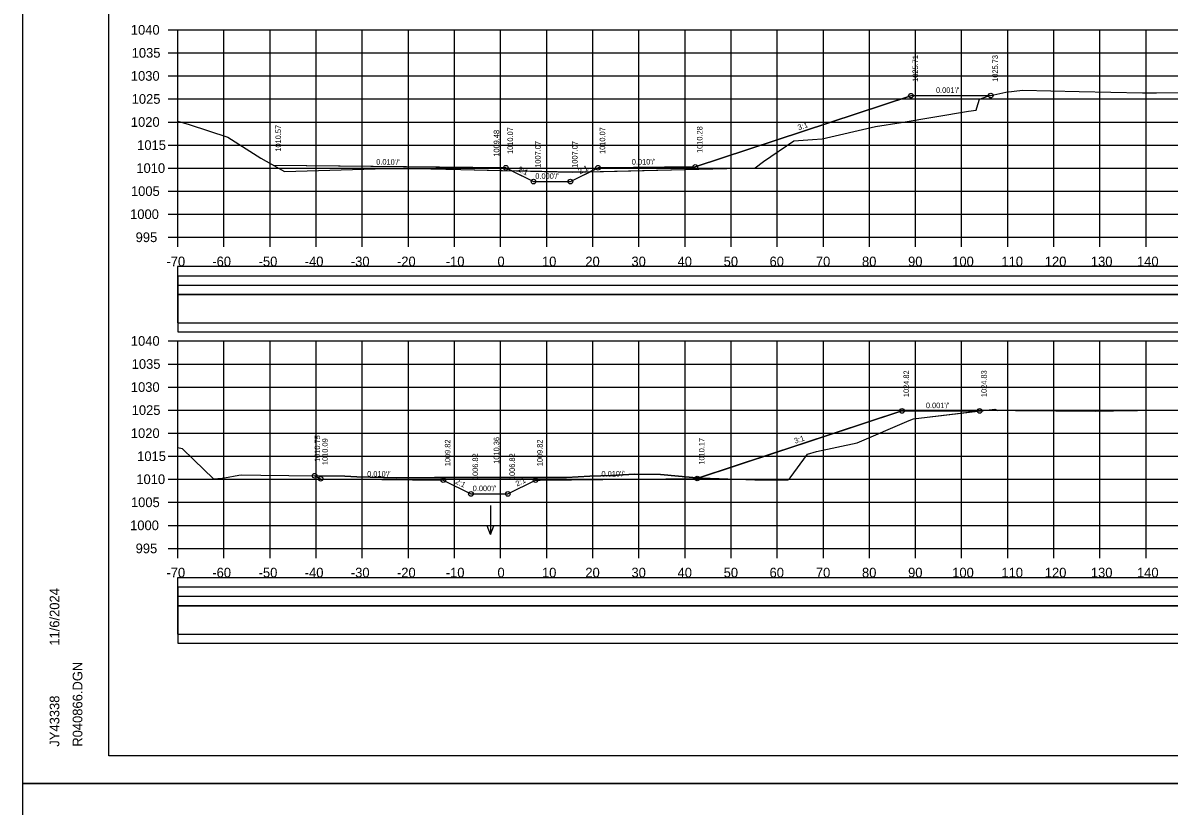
# Model space of a CAD drawing. Extents: x 1370565 to 1374448, y 301010 to 304637.
# Drawn here: x 1373947.9 to 1374196.5, y 302368.1 to 302538 of the extents above; entities that cross this region are included whole.
import ezdxf

# ---------------------------------------------------------------- set-up
doc = ezdxf.new("R2010")
doc.units = 0
for name, color, linetype in [('Default', 7, 'Continuous'), ('R_Axis', 7, 'Continuous'), ('R_Axis Annot', 7, 'Continuous'), ('R_Border', 7, 'Continuous'), ('R_Contours', 7, 'Continuous'), ('R_Drive', 7, 'Continuous'), ('R_Exist Surface', 7, 'Continuous'), ('R_Fin Surface', 7, 'Continuous'), ('R_Grid', 7, 'Continuous'), ('R_No Plot', 7, 'Continuous'), ('R_Water Annot', 7, 'Continuous'), ('R_Xsect Elev', 7, 'Continuous'), ('R_Xsect Slope', 7, 'Continuous')]:
    doc.layers.add(name, color=color, linetype=linetype)

msp = doc.modelspace()

# ---------------------------------------------------------------- linework, layer by layer
at = {"layer": 'Default'}
for points in [[(1373981.44, 302481.11), (1374421.61, 302481.11), (1374421.61, 302485.1), (1373981.44, 302485.1)], [(1373981.44, 302472.88), (1374421.61, 302472.88), (1374421.61, 302481.02), (1373981.44, 302481.02)], [(1373981.44, 302413.61), (1374421.61, 302413.61), (1374421.61, 302417.6), (1373981.44, 302417.6)], [(1373981.44, 302405.38), (1374421.61, 302405.38), (1374421.61, 302413.52), (1373981.44, 302413.52)]]:
    msp.add_lwpolyline(points, close=True, dxfattribs=at)
at = {"layer": 'R_Axis'}
for p, q in [((1373979.42, 302536.48), (1373981.52, 302536.48)), ((1373981.52, 302491.48), (1373981.52, 302536.48)), ((1373979.42, 302531.48), (1373981.52, 302531.48)), ((1373979.42, 302526.48), (1373981.52, 302526.48)), ((1373979.42, 302521.48), (1373981.52, 302521.48)), ((1373979.42, 302516.48), (1373981.52, 302516.48)), ((1373979.42, 302511.48), (1373981.52, 302511.48)), ((1373979.42, 302506.48), (1373981.52, 302506.48)), ((1373979.42, 302501.48), (1373981.52, 302501.48)), ((1373979.42, 302496.48), (1373981.52, 302496.48)), ((1373979.42, 302491.48), (1373981.52, 302491.48)), ((1373981.52, 302491.48), (1374421.52, 302491.48)), ((1373981.52, 302489.38), (1373981.52, 302491.48)), ((1373991.52, 302489.38), (1373991.52, 302491.48)), ((1374001.52, 302489.38), (1374001.52, 302491.48)), ((1374011.52, 302489.38), (1374011.52, 302491.48)), ((1374021.52, 302489.38), (1374021.52, 302491.48)), ((1374031.52, 302489.38), (1374031.52, 302491.48)), ((1374041.52, 302489.38), (1374041.52, 302491.48)), ((1374051.52, 302489.38), (1374051.52, 302491.48)), ((1374061.52, 302489.38), (1374061.52, 302491.48)), ((1374071.52, 302489.38), (1374071.52, 302491.48)), ((1374081.52, 302489.38), (1374081.52, 302491.48)), ((1374091.52, 302489.38), (1374091.52, 302491.48)), ((1374101.52, 302489.38), (1374101.52, 302491.48)), ((1374111.52, 302489.38), (1374111.52, 302491.48)), ((1374121.52, 302489.38), (1374121.52, 302491.48)), ((1374131.52, 302489.38), (1374131.52, 302491.48)), ((1374141.52, 302489.38), (1374141.52, 302491.48)), ((1374151.52, 302489.38), (1374151.52, 302491.48)), ((1374161.52, 302489.38), (1374161.52, 302491.48)), ((1374171.52, 302489.38), (1374171.52, 302491.48)), ((1374181.52, 302489.38), (1374181.52, 302491.48)), ((1374191.52, 302489.38), (1374191.52, 302491.48)), ((1373979.42, 302468.98), (1373981.52, 302468.98)), ((1373981.52, 302423.98), (1373981.52, 302468.98)), ((1373979.42, 302463.98), (1373981.52, 302463.98)), ((1373979.42, 302458.98), (1373981.52, 302458.98)), ((1373979.42, 302453.98), (1373981.52, 302453.98)), ((1373979.42, 302448.98), (1373981.52, 302448.98)), ((1373979.42, 302443.98), (1373981.52, 302443.98)), ((1373979.42, 302438.98), (1373981.52, 302438.98)), ((1373979.42, 302433.98), (1373981.52, 302433.98)), ((1373979.42, 302428.98), (1373981.52, 302428.98)), ((1373979.42, 302423.98), (1373981.52, 302423.98)), ((1373981.52, 302423.98), (1374421.52, 302423.98)), ((1373981.52, 302421.88), (1373981.52, 302423.98)), ((1373991.52, 302421.88), (1373991.52, 302423.98)), ((1374001.52, 302421.88), (1374001.52, 302423.98)), ((1374011.52, 302421.88), (1374011.52, 302423.98)), ((1374021.52, 302421.88), (1374021.52, 302423.98)), ((1374031.52, 302421.88), (1374031.52, 302423.98)), ((1374041.52, 302421.88), (1374041.52, 302423.98)), ((1374051.52, 302421.88), (1374051.52, 302423.98)), ((1374061.52, 302421.88), (1374061.52, 302423.98)), ((1374071.52, 302421.88), (1374071.52, 302423.98)), ((1374081.52, 302421.88), (1374081.52, 302423.98)), ((1374091.52, 302421.88), (1374091.52, 302423.98)), ((1374101.52, 302421.88), (1374101.52, 302423.98)), ((1374111.52, 302421.88), (1374111.52, 302423.98)), ((1374121.52, 302421.88), (1374121.52, 302423.98)), ((1374131.52, 302421.88), (1374131.52, 302423.98)), ((1374141.52, 302421.88), (1374141.52, 302423.98)), ((1374151.52, 302421.88), (1374151.52, 302423.98)), ((1374161.52, 302421.88), (1374161.52, 302423.98)), ((1374171.52, 302421.88), (1374171.52, 302423.98)), ((1374181.52, 302421.88), (1374181.52, 302423.98)), ((1374191.52, 302421.88), (1374191.52, 302423.98))]:
    msp.add_line(p, q, dxfattribs=at)
at = {"layer": 'R_Border'}
for p, q in [((1373966.52, 302378.98), (1373966.52, 302687.17)), ((1373966.52, 302378.98), (1373966.52, 302378.98)), ((1374440.79, 302378.98), (1373966.52, 302378.98))]:
    msp.add_line(p, q, dxfattribs=at)
at = {"layer": 'R_Contours'}
for p, q in [((1374051.52, 302506.56), (1374002.34, 302507.05)), ((1374051.52, 302505.96), (1374051.52, 302506.56)), ((1374052.66, 302506.55), (1374051.52, 302506.56)), ((1374051.52, 302506.56), (1374051.52, 302505.96)), ((1374051.52, 302505.96), (1374053.95, 302505.9)), ((1374053.95, 302505.9), (1374052.66, 302506.55)), ((1374053.95, 302505.9), (1374058.66, 302503.55)), ((1374070.9, 302505.67), (1374094.55, 302506.26)), ((1374094.52, 302439.26), (1374094.04, 302439.28)), ((1374094.52, 302439.26), (1374095.01, 302439.25))]:
    msp.add_line(p, q, dxfattribs=at)
for points in [[(1374157.83, 302522.21), (1374140.51, 302522.19), (1374093.75, 302506.76), (1374073.66, 302506.56), (1374072.66, 302506.55), (1374070.9, 302505.67)], [(1374094.55, 302506.26), (1374106.76, 302506.54), (1374108.54, 302507.88), (1374115.11, 302512.39), (1374119.2, 302512.69), (1374121.23, 302512.83), (1374132.86, 302515.53), (1374138.39, 302516.38), (1374153.01, 302518.8), (1374154.7, 302519.04), (1374154.84, 302519.57), (1374155.09, 302520.5), (1374155.38, 302521.44), (1374157.18, 302522.06), (1374157.83, 302522.21)], [(1374002.34, 302507.05), (1374004.67, 302505.73), (1374024.32, 302506.29), (1374027.89, 302506.39), (1374028.94, 302506.42), (1374036.39, 302506.33), (1374042.91, 302506.17), (1374051.52, 302505.96)], [(1374070.9, 302505.67), (1374067.07, 302505.58), (1374053.95, 302505.9)], [(1374058.66, 302503.55), (1374066.66, 302503.55), (1374070.9, 302505.67)], [(1374155.41, 302453.81), (1374138.56, 302453.8), (1374094.52, 302439.26)], [(1374095.01, 302439.25), (1374106.67, 302438.86), (1374112.23, 302438.83), (1374113.87, 302438.82), (1374114.3, 302439.25), (1374118.11, 302444.43), (1374120.07, 302444.99), (1374128.88, 302446.87), (1374140.14, 302451.73), (1374141.06, 302452.12), (1374142.25, 302452.25), (1374155.41, 302453.81)], [(1374094.04, 302439.28), (1374093.9, 302439.29), (1374093.21, 302439.36), (1374086.2, 302440.04), (1374080.55, 302440.11), (1374075.64, 302439.8), (1374070.87, 302439.62), (1374065.84, 302439.37), (1374065.44, 302439.34), (1374054.86, 302439.34), (1374051.52, 302439.34), (1374037.17, 302439.33), (1374029.02, 302439.31), (1374020.34, 302439.53), (1374017.73, 302439.64), (1374011.17, 302439.73)], [(1374011.17, 302439.73), (1374012.49, 302439.06), (1374039.08, 302438.8), (1374045.08, 302435.8), (1374053.08, 302435.8), (1374059.08, 302438.8), (1374060.08, 302438.81), (1374094.18, 302439.15), (1374094.52, 302439.26)]]:
    msp.add_lwpolyline(points, dxfattribs=at)
at = {"layer": 'R_Drive'}
for points in [[(1373981.52, 302479.07), (1374421.73, 302479.07), (1374421.73, 302483.07), (1373981.52, 302483.07)], [(1373981.52, 302470.93), (1374421.73, 302470.93), (1374421.73, 302479.07), (1373981.52, 302479.07)], [(1373981.52, 302411.55), (1374421.73, 302411.55), (1374421.73, 302415.54), (1373981.52, 302415.54)], [(1373981.52, 302403.4), (1374421.66, 302403.4), (1374421.66, 302411.55), (1373981.52, 302411.55)]]:
    msp.add_lwpolyline(points, close=True, dxfattribs=at)
at = {"layer": 'R_Exist Surface'}
for points in [[(1373981.52, 302516.69), (1373983.97, 302515.94), (1373992.38, 302513.17), (1373999.5, 302508.66), (1374004.67, 302505.73), (1374024.32, 302506.29), (1374027.89, 302506.39), (1374028.94, 302506.42), (1374036.39, 302506.33), (1374042.91, 302506.17), (1374067.07, 302505.58), (1374094.55, 302506.26), (1374106.76, 302506.54), (1374108.54, 302507.88), (1374115.11, 302512.39), (1374119.2, 302512.69), (1374121.23, 302512.83), (1374132.86, 302515.53), (1374138.39, 302516.38), (1374153.01, 302518.8), (1374154.7, 302519.04), (1374154.84, 302519.57), (1374155.09, 302520.5), (1374155.38, 302521.44), (1374157.18, 302522.06), (1374161.07, 302522.95), (1374164.74, 302523.39), (1374176.99, 302523.11), (1374190.74, 302522.8), (1374193.8, 302522.8), (1374216.53, 302523.07)], [(1373981.52, 302445.9), (1373982.47, 302445.63), (1373984.96, 302443.18), (1373989.24, 302439.05), (1373991.1, 302439.22), (1373991.67, 302439.26), (1373994.72, 302439.83), (1373995.38, 302439.94), (1373999.49, 302439.87), (1374017.73, 302439.64), (1374020.34, 302439.53), (1374029.02, 302439.31), (1374037.17, 302439.33), (1374054.86, 302439.34), (1374065.44, 302439.34), (1374065.84, 302439.37), (1374070.87, 302439.62), (1374075.64, 302439.8), (1374080.55, 302440.11), (1374086.2, 302440.04), (1374093.21, 302439.36), (1374093.9, 302439.29), (1374094.04, 302439.28), (1374095.01, 302439.25), (1374106.67, 302438.86), (1374112.23, 302438.83), (1374113.87, 302438.82), (1374114.3, 302439.25), (1374118.11, 302444.43), (1374120.07, 302444.99), (1374128.88, 302446.87), (1374140.14, 302451.73), (1374141.06, 302452.12), (1374142.25, 302452.25), (1374158.71, 302454.2), (1374159.21, 302454), (1374159.32, 302453.86), (1374160.71, 302453.93), (1374163.18, 302453.87), (1374180.6, 302453.73), (1374184.48, 302453.83), (1374194.86, 302453.99), (1374210.81, 302454.28)]]:
    msp.add_lwpolyline(points, dxfattribs=at)
at = {"layer": 'R_Fin Surface'}
msp.add_line((1374052.66, 302506.55), (1374002.34, 302507.05), dxfattribs=at)
for points in [[(1374052.66, 302506.55), (1374058.66, 302503.55), (1374066.66, 302503.55), (1374072.66, 302506.55), (1374073.66, 302506.56), (1374093.75, 302506.76), (1374140.51, 302522.19), (1374157.83, 302522.21)], [(1374011.17, 302439.73), (1374012.49, 302439.06), (1374039.08, 302438.8), (1374045.08, 302435.8), (1374053.08, 302435.8), (1374059.08, 302438.8), (1374060.08, 302438.81), (1374094.18, 302439.15), (1374138.56, 302453.8), (1374155.41, 302453.81)]]:
    msp.add_lwpolyline(points, dxfattribs=at)
at = {"layer": 'R_Grid'}
for p, q in [((1373981.52, 302536.48), (1374421.52, 302536.48)), ((1373981.52, 302491.48), (1373981.52, 302536.48)), ((1373991.52, 302491.48), (1373991.52, 302536.48)), ((1374001.52, 302491.48), (1374001.52, 302536.48)), ((1374011.52, 302491.48), (1374011.52, 302536.48)), ((1374021.52, 302491.48), (1374021.52, 302536.48)), ((1374031.52, 302491.48), (1374031.52, 302536.48)), ((1374041.52, 302491.48), (1374041.52, 302536.48)), ((1374051.52, 302491.48), (1374051.52, 302536.48)), ((1374061.52, 302491.48), (1374061.52, 302536.48)), ((1374071.52, 302491.48), (1374071.52, 302536.48)), ((1374081.52, 302491.48), (1374081.52, 302536.48)), ((1374091.52, 302491.48), (1374091.52, 302536.48)), ((1374101.52, 302491.48), (1374101.52, 302536.48)), ((1374111.52, 302491.48), (1374111.52, 302536.48)), ((1374121.52, 302491.48), (1374121.52, 302536.48)), ((1374131.52, 302491.48), (1374131.52, 302536.48)), ((1374141.52, 302491.48), (1374141.52, 302536.48)), ((1374151.52, 302491.48), (1374151.52, 302536.48)), ((1374161.52, 302491.48), (1374161.52, 302536.48)), ((1374171.52, 302491.48), (1374171.52, 302536.48)), ((1374181.52, 302491.48), (1374181.52, 302536.48)), ((1374191.52, 302491.48), (1374191.52, 302536.48)), ((1373981.52, 302531.48), (1374421.52, 302531.48)), ((1373981.52, 302526.48), (1374421.52, 302526.48)), ((1373981.52, 302521.48), (1374421.52, 302521.48)), ((1373981.52, 302516.48), (1374421.52, 302516.48)), ((1373981.52, 302511.48), (1374421.52, 302511.48)), ((1373981.52, 302506.48), (1374421.52, 302506.48)), ((1373981.52, 302501.48), (1374421.52, 302501.48)), ((1373981.52, 302496.48), (1374421.52, 302496.48)), ((1373981.52, 302491.48), (1374421.52, 302491.48)), ((1373981.52, 302468.98), (1374421.52, 302468.98)), ((1373981.52, 302423.98), (1373981.52, 302468.98)), ((1373991.52, 302423.98), (1373991.52, 302468.98)), ((1374001.52, 302423.98), (1374001.52, 302468.98)), ((1374011.52, 302423.98), (1374011.52, 302468.98)), ((1374021.52, 302423.98), (1374021.52, 302468.98)), ((1374031.52, 302423.98), (1374031.52, 302468.98)), ((1374041.52, 302423.98), (1374041.52, 302468.98)), ((1374051.52, 302423.98), (1374051.52, 302468.98)), ((1374061.52, 302423.98), (1374061.52, 302468.98)), ((1374071.52, 302423.98), (1374071.52, 302468.98)), ((1374081.52, 302423.98), (1374081.52, 302468.98)), ((1374091.52, 302423.98), (1374091.52, 302468.98)), ((1374101.52, 302423.98), (1374101.52, 302468.98)), ((1374111.52, 302423.98), (1374111.52, 302468.98)), ((1374121.52, 302423.98), (1374121.52, 302468.98)), ((1374131.52, 302423.98), (1374131.52, 302468.98)), ((1374141.52, 302423.98), (1374141.52, 302468.98)), ((1374151.52, 302423.98), (1374151.52, 302468.98)), ((1374161.52, 302423.98), (1374161.52, 302468.98)), ((1374171.52, 302423.98), (1374171.52, 302468.98)), ((1374181.52, 302423.98), (1374181.52, 302468.98)), ((1374191.52, 302423.98), (1374191.52, 302468.98)), ((1373981.52, 302463.98), (1374421.52, 302463.98)), ((1373981.52, 302458.98), (1374421.52, 302458.98)), ((1373981.52, 302453.98), (1374421.52, 302453.98)), ((1373981.52, 302448.98), (1374421.52, 302448.98)), ((1373981.52, 302443.98), (1374421.52, 302443.98)), ((1373981.52, 302438.98), (1374421.52, 302438.98)), ((1373981.52, 302433.98), (1374421.52, 302433.98)), ((1373981.52, 302428.98), (1374421.52, 302428.98)), ((1373981.52, 302423.98), (1374421.52, 302423.98))]:
    msp.add_line(p, q, dxfattribs=at)
at = {"layer": 'R_No Plot'}
for p, q in [((1373947.92, 302373.01), (1374447.92, 302373.01)), ((1373947.92, 302373), (1374447.92, 302373))]:
    msp.add_line(p, q, dxfattribs=at)
for points in [[(1373947.91, 302693.01), (1374447.92, 302693.01), (1374447.92, 302373), (1373947.91, 302373)], [(1374317.4, 302687.17), (1374346.83, 302687.17), (1374346.83, 302672.35), (1374371, 302672.35), (1374405.8, 302672.35), (1374405.98, 302630.11), (1374440.79, 302630.11), (1374440.79, 302378.98), (1373966.52, 302378.98), (1373966.52, 302687.17)], [(1373947.91, 302373), (1374447.92, 302373), (1374447.92, 302053), (1373947.91, 302053)]]:
    msp.add_lwpolyline(points, close=True, dxfattribs=at)
for centre in [(1374157.83, 302522.21), (1374140.51, 302522.19), (1374052.66, 302506.55), (1374072.66, 302506.55), (1374093.75, 302506.76), (1374058.66, 302503.55), (1374066.66, 302503.55), (1374138.56, 302453.8), (1374155.41, 302453.81), (1374011.17, 302439.73), (1374012.49, 302439.06), (1374039.08, 302438.8), (1374059.08, 302438.8), (1374094.18, 302439.15), (1374045.08, 302435.8), (1374053.08, 302435.8)]:
    msp.add_circle(centre, 0.5, dxfattribs=at)
at = {"layer": 'R_Water Annot'}
for p, q in [((1374049.33, 302433.26), (1374049.33, 302426.97)), ((1374049.33, 302426.97), (1374048.63, 302428.9)), ((1374049.33, 302426.97), (1374050.03, 302428.9))]:
    msp.add_line(p, q, dxfattribs=at)
at = {"layer": 'R_Xsect Elev'}
for p, q in [((1374051.52, 302505.96), (1374051.52, 302515.96)), ((1374051.52, 302439.34), (1374051.52, 302449.34))]:
    msp.add_line(p, q, dxfattribs=at)

# ---------------------------------------------------------------- texts
at = {"layer": 'R_Axis Annot'}
for s, p in [('1040', (1373971.32, 302535.43)), ('1035', (1373971.5, 302530.43)), ('1030', (1373971.32, 302525.43)), ('1025', (1373971.5, 302520.43)), ('1020', (1373971.32, 302515.43)), ('1015', (1373972.69, 302510.43)), ('1010', (1373972.51, 302505.43)), ('1005', (1373971.34, 302500.43)), ('1000', (1373971.16, 302495.43)), ('995', (1373972.36, 302490.43)), ('-70', (1373979.04, 302485.18)), ('-60', (1373988.99, 302485.18)), ('-50', (1373999.04, 302485.18)), ('-40', (1374009.04, 302485.18)), ('-30', (1374019.04, 302485.18)), ('-20', (1374029.04, 302485.18)), ('-10', (1374039.63, 302485.18)), ('0', (1374050.84, 302485.18)), ('10', (1374060.49, 302485.18)), ('20', (1374069.9, 302485.18)), ('30', (1374079.9, 302485.18)), ('40', (1374089.9, 302485.18)), ('50', (1374099.9, 302485.18)), ('60', (1374109.85, 302485.18)), ('70', (1374119.9, 302485.18)), ('80', (1374129.9, 302485.18)), ('90', (1374139.9, 302485.18)), ('100', (1374149.47, 302485.18)), ('110', (1374160.14, 302485.18)), ('120', (1374169.55, 302485.18)), ('130', (1374179.55, 302485.18)), ('140', (1374189.55, 302485.18)), ('1040', (1373971.32, 302467.93)), ('1035', (1373971.5, 302462.93)), ('1030', (1373971.32, 302457.93)), ('1025', (1373971.5, 302452.93)), ('1020', (1373971.32, 302447.93)), ('1015', (1373972.69, 302442.93)), ('1010', (1373972.51, 302437.93)), ('1005', (1373971.34, 302432.93)), ('1000', (1373971.16, 302427.93)), ('995', (1373972.36, 302422.93)), ('-70', (1373979.04, 302417.68)), ('-60', (1373988.99, 302417.68)), ('-50', (1373999.04, 302417.68)), ('-40', (1374009.04, 302417.68)), ('-30', (1374019.04, 302417.68)), ('-20', (1374029.04, 302417.68)), ('-10', (1374039.63, 302417.68)), ('0', (1374050.84, 302417.68)), ('10', (1374060.49, 302417.68)), ('20', (1374069.9, 302417.68)), ('30', (1374079.9, 302417.68)), ('40', (1374089.9, 302417.68)), ('50', (1374099.9, 302417.68)), ('60', (1374109.85, 302417.68)), ('70', (1374119.9, 302417.68)), ('80', (1374129.9, 302417.68)), ('90', (1374139.9, 302417.68)), ('100', (1374149.47, 302417.68)), ('110', (1374160.14, 302417.68)), ('120', (1374169.55, 302417.68)), ('130', (1374179.55, 302417.68)), ('140', (1374189.55, 302417.68))]:
    msp.add_text(s, height=2.1, dxfattribs=at).set_placement(p)
at = {"layer": 'R_Border'}
for s, p in [('11/6/2024', (1373955.82, 302402.87)), ('R040866.DGN', (1373960.81, 302380.96)), ('JY43338', (1373955.82, 302380.96))]:
    msp.add_text(s, height=2.1, rotation=90, dxfattribs=at).set_placement(p)
at = {"layer": 'R_Xsect Elev'}
for s, rotation, p in [('1025.71', 90, (1374142.06, 302525.19)), ('1025.73', 90, (1374159.38, 302525.21)), ('1010.57', 90, (1374003.89, 302510.05)), ('1010.07', 90, (1374054.21, 302509.55)), ('1010.07', 90, (1374074.21, 302509.55)), ('1010.28', 90, (1374095.3, 302509.76)), ('1009.48', 90, (1374051.22, 302508.96)), ('1007.07', 90, (1374060.21, 302506.55)), ('1007.07', 90, (1374068.21, 302506.55)), ("0.010'/'", 359.4271, (1374024.54, 302507.24)), ('1024.82', 90, (1374140.11, 302456.8)), ('1024.83', 90, (1374156.96, 302456.81)), ('1010.75', 90, (1374012.37, 302442.73)), ('1010.09', 90, (1374014.04, 302442.06)), ('1009.82', 90, (1374040.63, 302441.8)), ('1010.36', 90, (1374051.22, 302442.34)), ('1009.82', 90, (1374060.63, 302441.8)), ('1010.17', 90, (1374095.73, 302442.15)), ('1006.82', 90, (1374046.63, 302438.8)), ('1006.82', 90, (1374054.63, 302438.8))]:
    msp.add_text(s, height=1.2, rotation=rotation, dxfattribs=at).set_placement(p)
at = {"layer": 'R_Xsect Slope'}
for s, rotation, p in [("0.001'/'", 0.0573, (1374145.95, 302522.79)), ('3:1', 18.2629, (1374116.19, 302514.69)), ("0.010'/'", 0.5729, (1374079.98, 302507.22)), ('2:1', 333.4349, (1374055.14, 302505.87)), ("0.000'/'", 360, (1374059.05, 302504.15)), ('2:1', 26.5651, (1374068.69, 302505.12)), ("0.001'/'", 0.0573, (1374143.76, 302454.4)), ('3:1', 18.2629, (1374115.42, 302446.69)), ("0.010'/'", 359.4271, (1374022.57, 302439.56)), ("0.010'/'", 0.5729, (1374073.4, 302439.54)), ('2:1', 333.4349, (1374041.56, 302438.12)), ('2:1', 26.5651, (1374055.11, 302437.37)), ("0.000'/'", 360, (1374045.47, 302436.4))]:
    msp.add_text(s, height=1.2, rotation=rotation, dxfattribs=at).set_placement(p)

doc.saveas('drawing.dxf')
